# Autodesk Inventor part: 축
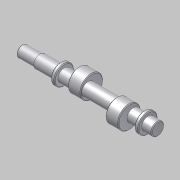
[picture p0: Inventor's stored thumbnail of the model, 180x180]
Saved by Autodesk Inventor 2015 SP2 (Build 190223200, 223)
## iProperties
Created: 2013-02
Part Number: 축
Document SubType Name: Modeling
Designer: 한국산업디자인학원[gmhk.co.kr]
Density: 1 g/cm^3
Material: 일반
Appearance: 기본값
Mass: 58.3378 g
Surface Area: 143.366 cm^2
Volume: 58.3378 cm^3
Author: 한국산업디자인학원[gmhk.co.kr]
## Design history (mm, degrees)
sketch "스케치2"
  geometry: L1 (-58, 84.5)-(-58, 15.5) reference; L2 (58, 15.5)-(58, 84.5) reference; L3 (-85, 25.774)-(-85, 74.226) reference; L4 (70, 84.185)-(70, 15.815) reference; L5 (71, 50)-(-109, 50); L6 (69.4, 58.5)-(58.6, 58.5) reference; L7 (71, 50)-(71, 58.5); L8 (71, 58.5)-(58, 58.5); L9 (58, 58.5)-(58, 63); L10 (58, 63)-(53, 63); L11 (53, 63)-(53, 58.5); L12 (53, 58.5)-(-53, 58.5); L13 (-53, 58.5)-(-53, 63); L14 (-53, 63)-(-58, 63); L15 (-58, 63)-(-58, 58.5); L16 (-58, 58.5)-(-85, 58.5); L17 (-85, 58.5)-(-85, 57.5); L18 (-85, 57.5)-(-109, 57.5); L19 (-109, 57.5)-(-109, 50); L20 (-30, 102.5)-(-30, 50); L21 (30, 102.5)-(30, 50); L22 (-50, 102.5)-(-10, 102.5) reference; L23 (10, 102.5)-(50, 102.5) reference; 2 further points
  constraints: 34 end point, 10 perpendicular, 9 point on line, 5 collinear, 3 midpoint, 3 parallel, 1 horizontal, 2 other
  dimensions: "d0" = 1 distance between parallel lines of L7 L4; "d1" = 26 diameter of L10 L5; "d2" = 5 distance of L9.end L10.end; "d3" = 5 distance of L13.end L14.end (= d2); "d4" = 180 distance of L5.start L5.end; "d5" = 15 diameter of L18 L5
  node "참조1"
  node "참조2"
  node "참조3"
  node "참조4"
  node "참조7"
  node "참조8"
revolve "회전1" stored, may be unused: angle "d6" = 90 deg
node "작업 평면1"
sketch "스케치3"
  geometry: C1 r 8.5 at (52.5, 0) reference; C2 r 15 at (47.5, 0); 1 further point
  constraints: 1 centre point, 1 horizontal alignment
  dimensions: "d8" = 5 distance of C1.centre C2.centre; "d9" = 30 diameter of C2
extrude "돌출1" join sketch "스케치3" stored distance "d10" = 17; taper "d11" = 0 deg
node "작업 평면2"
sketch "스케치4"
  geometry: C1 r 8.5 at (52.5, 0) reference; C2 r 15 at (57.5, 0); 1 further point
  constraints: 1 centre point, 1 horizontal alignment
  dimensions: "d13" = 5 distance of C2.centre C1.centre; "d14" = 30 diameter of C2
extrude "돌출2" join sketch "스케치4" stored distance "d15" = 17; taper "d16" = 0 deg
chamfer "모따기1" distance "d17" = 1; stored, may be unused: second distance "d18" = 2, angle "d19" = 45 deg
node "작업 평면3"
sketch "스케치5"
  geometry: L1 (12, 6.5)-(12, -6.5) reference; L2 (12, 2.5)-(-5.5, 2.5); L3 (-5.5, -2.5)-(12, -2.5); A1 r 2.5 centre (-5.5, 0) between (-5.5, 2.5) and (-5.5, -2.5); 2 further points
  constraints: 4 end point, 2 point on circle, 2 point on line, 2 tangent, 1 centre point, 1 horizontal alignment, 1 midpoint, 1 parallel, 1 perpendicular
  dimensions: "d20" = 5 distance between parallel lines of L3 L2; "d21" = 20 dimension on A1 L1
extrude "돌출3" cut sketch "스케치5" distance "d22" = 3; taper "d23" = 0 deg
chamfer "모따기2" distance "d24" = 1; stored, may be unused: second distance "d25" = 2, angle "d26" = 45 deg
node "솔리드1"
node "투영된 루프1"
node "투영된 루프2"
other parameters: "d7" = 0, "d12" = 0
